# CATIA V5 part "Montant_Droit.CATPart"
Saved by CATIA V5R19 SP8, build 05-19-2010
Part number: Montant_Droit
Nomenclature: 3
Material "Acier": density 7860 kg/m3, Young's modulus 2e+11 Pa, Poisson ratio 0.266, thermal expansion 1.17e-05 1/K
Bounding box of the stored display mesh (mm): x -80.5 to 22.481, y -67.011 to 64.472, z 0 to 1194.396
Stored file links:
  C:\Users\rphgr\Desktop\0_Tapis_TC520B_vitesse\Montant_Droit.CATPart
  D:\Programmes\DassaultSysteme\win_b64\reffiles\standard\MetricThickPitch.txt
  D:\Programmes\DassaultSysteme\win_b64\startup\materials\French\Catalog.CATMaterial
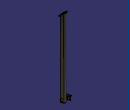
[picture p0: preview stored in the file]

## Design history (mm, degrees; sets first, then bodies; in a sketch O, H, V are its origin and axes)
AxisSystem1: origin (0, 0, 0), X (1, 0, 0), Y (0, 1, 0), Z (0, 0, 1)
Body1 (main body), material "Acier"
  Sketch1 on XY plane of AxisSystem1, origin (0, 0, 0), H (1, 0, 0), V (0, 1, 0)
    construction line L1 (0, 20) -> (0, -20)
    point P1 (0, 20)
    point P2 (0, -20)
    line L2 (20, 20) -> (20, -20)
    line L3 (-20, -20) -> (-20, 20)
    arc A1 centre (0, -20) radius 20 from (20, -20) to (-20, -20) cw
    arc A2 centre (0, 20) radius 20 from (-20, 20) to (20, 20) cw
    distance L1 L2 = 20
    length L1 = 40
    distance P2 O = 20
    coincidence: P1 V
    vertical: L1 V
    tangency: A1 L2, A2 L2, A1 L3, A2 L3
  Pad1: profile Sketch1, direction (0, 0, 1), length 1220, thin wall 1.5
  Sketch2 on YZ plane of AxisSystem1, origin (0, 0, 0), H (0, 1, 0), V (0, 0, 1)
    line L1 (-40, 1110) -> (-40, 0)
    point P2 (-40, 0)
    line L2 (-40, 0) -> (40, 21.4359)
    line L3 (40, 21.4359) -> (40, 1190)
    line L4 (40, 1190) -> (-40, 1110)
    reference intersected line E1 through (0, 0) direction (-1, 0) from XY plane of AxisSystem1
    distance P2 O = 40
    distance L1 L3 = 80
    angle L1 L2 = 75
    length L1 = 1110
    angle L4 L3 = 45
    vertical: L1 V
    coincidence: P2 E1
  Pocket1: profile Sketch2, direction (-1, 0, 0), through (limit type 3), opposite side through (limit type 3), outer side
  Sketch3 on face of Pad1, origin (18.5, 0, 0), H (0, -1, 0), V (0, 0, 1)
    line L1 (-17, 61.6004) -> (17, 61.6004)
    line L2 (20, 58.6004) -> (20, 24.6004)
    line L3 (17, 21.6004) -> (-17, 21.6004)
    line L4 (-20, 24.6004) -> (-20, 58.6004)
    arc A1 centre (-17, 58.6004) radius 3 from (-17, 61.6004) to (-20, 58.6004) ccw
    arc A2 centre (17, 58.6004) radius 3 from (17, 61.6004) to (20, 58.6004) cw
    arc A3 centre (17, 24.6004) radius 3 from (20, 24.6004) to (17, 21.6004) cw
    arc A4 centre (-17, 24.6004) radius 3 from (-17, 21.6004) to (-20, 24.6004) cw
    distance L2 L4 = 40
    distance L3 L1 = 40
    radius A1 = 3
    radius A2 = 3
    radius A3 = 3
    radius A4 = 3
    distance L4 V = 20
    horizontal: L1 H, L3 H
    vertical: L2 V, L4 V
    tangency: A1 L1, A1 L4, A2 L1, A2 L2, A3 L2, A3 L3, A4 L3, A4 L4
  Pad2: profile Sketch3, direction (-1, 0, 0), length 67, thin wall 1.5
  Sketch4 on face of Pad1, origin (-20, 0, 0), H (0, -1, 0), V (0, 0, 1)
  Pocket2: profile Sketch4, direction (1, 0, 0), through (limit type 6)
  Sketch5 on face of Pad2, origin (0, 0, 21.6004), H (1, 0, 0), V (0, -1, 0)
    construction line L1 (-4, 0) -> (4, 0)
    point P2 (4, 0)
    line L2 (-4, 8) -> (4, 8)
    line L3 (4, -8) -> (-4, -8)
    arc A1 centre (4, 0) radius 8 from (4, 8) to (4, -8) cw
    arc A2 centre (-4, 0) radius 8 from (-4, -8) to (-4, 8) cw
    reference intersected line E1 through (0, 0) direction (0, 1) from YZ plane of AxisSystem1
    distance L1 L2 = 8
    length L1 = 8
    distance P2 E1 = 4
    horizontal: L1 H
    tangency: A1 L2, A2 L2, A1 L3, A2 L3
    coincidence: L1 H
  Pocket3: profile Sketch5, direction (0, 0, 1), through (limit type 3)
  Plane1: type Angle, RefPlane face of Pocket1 from Sketch2.L2, Direction edge [XY plane of AxisSystem1 | ZX plane of AxisSystem1], Angle 90
  Sketch6 on Plane1, origin (0, 0, 0), H (1, 0, 0), V (0, -0.2588, 0.9659)
    point P1 (-80.5, 65.3528)
    line L1 (-80.5, 65.3528) -> (-54.5, 65.3528)
    arc A1 centre (-54.5, 59.3528) radius 6 from (-54.5, 65.3528) to (-48.5, 59.3528) cw
    line L2 (-48.5, 59.3528) -> (-48.5, 20.3528)
    point P5 (-48.5, 20.3528)
    reference intersected line E1 through (-48.5, 0) direction (0, -1) from end face of Pad2
    reference intersected line E2 through (0, 10.3528) direction (-1, 0) from face of Pocket1 from Sketch2.L2
    angle L1 L2 = 90
    distance P5 L1 = 45
    distance P1 L2 = 32
    radius A1 = 6
    distance P5 E2 = 10
    tangency: A1 L1, L2 A1
    coincidence: L2 E1
  Pad3: profile Sketch6, direction (0, -0.9659, -0.2588), length 51.864, opposite side length 73.136, thin wall 4
  Fillet1: radius 4, on edge [face of Pad3 | end face of Pad3] (x2); edge [start face of Pad3 | face of Pad3] (x2)
  Sketch7 on face of Pad3, origin (-52.5, 0, 0), H (0, -1, 0), V (0, 0, 1)
    construction line L1 (47.6556, 23.8306) -> (46.8792, 20.9328)
    point P2 (46.8792, 20.9328)
    line L2 (52.0023, 22.6659) -> (51.2258, 19.7681)
    line L3 (42.5325, 22.0975) -> (43.309, 24.9953)
    arc A1 centre (46.8792, 20.9328) radius 4.5 from (51.2258, 19.7681) to (42.5325, 22.0975) cw
    arc A2 centre (47.6556, 23.8306) radius 4.5 from (43.309, 24.9953) to (52.0023, 22.6659) cw
    construction line L4 (-48.9369, 49.7125) -> (-49.7134, 46.8147)
    point P8 (-49.7134, 46.8147)
    line L5 (-44.5903, 48.5478) -> (-45.3667, 45.65)
    line L6 (-54.0601, 47.9794) -> (-53.2836, 50.8772)
    arc A3 centre (-49.7134, 46.8147) radius 4.5 from (-45.3667, 45.65) to (-54.0601, 47.9794) cw
    arc A4 centre (-48.9369, 49.7125) radius 4.5 from (-53.2836, 50.8772) to (-44.5903, 48.5478) cw
    reference intersected line E1 (66.9225, 49.3711) -> (55.3645, 6.2359) from end face of Pad3
    reference intersected line E2 (65.638, 3.4831) -> (-55.1027, 35.8354) from face of Pad3
    reference intersected line E3 (65.638, 3.4831) -> (-55.1027, 35.8354) from face of Pad3
    construction line L7 (-4.6593, 43.0247) -> (5, 40.4365)
    point P14 (5, 40.4365)
    line L8 (-2.0711, 52.684) -> (7.5882, 50.0958)
    line L9 (2.4118, 30.7772) -> (-7.2474, 33.3654)
    arc A5 centre (5, 40.4365) radius 10 from (7.5882, 50.0958) to (2.4118, 30.7772) cw
    arc A6 centre (-4.6593, 43.0247) radius 10 from (-7.2474, 33.3654) to (-2.0711, 52.684) cw
    reference intersected line E4 (65.638, 3.4831) -> (-55.1027, 35.8354) from face of Pad3
    distance L1 L2 = 4.5
    distance L4 L5 = 4.5
    length L1 = 3
    length L4 = 3
    distance L4 L1 = 100
    distance L1 E1 = 12
    distance P2 E2 = 12
    distance P8 E3 = 12
    distance L7 L8 = 10
    distance L7 E4 = 20
    length L7 = 10
    distance P14 V = 5
    tangency: A1 L2, A2 L2, A1 L3, A2 L3, A3 L5, A4 L5, A3 L6, A4 L6, A5 L8, A6 L8, A5 L9, A6 L9
    perpendicularity: L7 L3
  Pocket4: profile Sketch7, direction (1, 0, 0), through (limit type 6)
  Sketch8 on face of Pad3, origin (0, -15.8793, 59.2622), H (-1, 0, 0), V (0, 0.9659, 0.2588)
    construction line L1 (66.8047, 54.136) -> (66.8047, 52.136)
    point P1 (66.8047, 54.136)
    line L2 (71.3047, 54.136) -> (71.3047, 52.136)
    line L3 (62.3047, 52.136) -> (62.3047, 54.136)
    arc A1 centre (66.8047, 52.136) radius 4.5 from (71.3047, 52.136) to (62.3047, 52.136) cw
    arc A2 centre (66.8047, 54.136) radius 4.5 from (62.3047, 54.136) to (71.3047, 54.136) cw
    construction line L4 (66.8047, -30.864) -> (66.8047, -32.864)
    point P7 (66.8047, -30.864)
    point P8 (66.8047, -32.864)
    line L5 (71.3047, -30.864) -> (71.3047, -32.864)
    line L6 (62.3047, -32.864) -> (62.3047, -30.864)
    arc A3 centre (66.8047, -32.864) radius 4.5 from (71.3047, -32.864) to (62.3047, -32.864) cw
    arc A4 centre (66.8047, -30.864) radius 4.5 from (62.3047, -30.864) to (71.3047, -30.864) cw
    reference intersected line E1 (80.5, 73.136) -> (80.5, -51.864) from face of Pad3
    reference intersected line E2 (80.5, -51.864) -> (48.8431, -51.864) from end face of Pad3
    reference projected line E3 (80.5, 73.136) -> (54.5, 73.136) from edge [face of Pad3 | start face of Pad3]
    distance L1 L2 = 4.5
    distance L4 L5 = 4.5
    distance L1 E1 = 13.6953
    length L1 = 2
    length L4 = 2
    distance P8 E2 = 19
    distance P1 E3 = 19
    vertical: L1 V, L4 V
    tangency: A1 L2, A2 L2, A1 L3, A2 L3, A3 L5, A4 L5, A3 L6, A4 L6
    coincidence: P7 L1
  Pocket5: profile Sketch8, direction (0, -0.2588, 0.9659), through (limit type 6)
  Plane2: type Normal, Curve edge [face of Pocket1 from Sketch2.L4 | face of Pad1], RefPoint vertex [face of Pad1 | face of Pocket1 from Sketch2.L4 | face of Pad1]
  Plane3: type Offset, RefPlane face of Pocket1 from Sketch2.L4, Offset 0, reversed
  Sketch9 on Plane2, origin (0, 555, 555), H (-1, 0, 0), V (0, -0.7071, 0.7071)
    arc A1 centre (0, 824.5306) radius 23 from (-22.5834, 820.1728) to (22.5834, 820.1728) ccw
    point P1 (0, 824.5306)
    reference projected point E1 (-20, 813.1728) from edge [face of Pocket1 from Sketch2.L4 | face of Pad1]
    axis line L1 (-28.642, 820.1728) -> (24.6976, 820.1728)
    reference intersected line E2 through (0, 813.1728) direction (1, 0) from face of Pocket1 from Sketch2.L4
    point P4 (22.5834, 820.1728)
    point P5 (-22.5834, 820.1728)
    radius A1 = 23
    distance L1 E2 = 7
    coincidence: P1 V, A1 E1, L1 P4, L1 P5
    horizontal: L1 H
  Pad4: profile Sketch9, direction (0, -0.7071, -0.7071), length 41, opposite side length 95, thin wall 3
  Sketch10 on Plane2, origin (0, 555, 555), H (-1, 0, 0), V (0, -0.7071, 0.7071)
    projected arc E1 centre (0, 824.5306) radius 20 from (-19.6377, 820.7412) to (19.6377, 820.7412) ccw from edge [start face of Pad4 | face of Pad4]
  Pocket6: profile Sketch10, direction (0, 0.7071, 0.7071), length 91, opposite side length 71
  Fillet2: radius 20, on edge [face of Pad4 | start face of Pad4] (x2); edge [end face of Pad4 | face of Pad4] (x2)
  Fillet3: radius 0.5, on face of Pad4
  Sketch11 on Plane3, origin (0, -575, 575), H (-1, 0, 0), V (0, 0.7071, 0.7071)
    construction line L1 (0, 818.1728) -> (0, 808.1728)
    point P1 (0, 818.1728)
    line L2 (10, 818.1728) -> (10, 808.1728)
    line L3 (-10, 808.1728) -> (-10, 818.1728)
    arc A1 centre (0, 808.1728) radius 10 from (10, 808.1728) to (-10, 808.1728) cw
    arc A2 centre (0, 818.1728) radius 10 from (-10, 818.1728) to (10, 818.1728) cw
    reference intersected line E1 through (0, 0) direction (0, -1) from YZ plane of AxisSystem1
    reference intersected line E2 through (0, 813.1728) direction (-1, 0) from ZX plane of AxisSystem1
    distance L1 L2 = 10
    length L1 = 10
    distance P1 E2 = 5
    vertical: L1 V
    tangency: A1 L2, A2 L2, A1 L3, A2 L3
    coincidence: L1 E1
  Pocket7: profile Sketch11, direction (0, -0.7071, 0.7071), length 22, mirrored extent
  Sketch12 on Plane3, origin (5.7218, 33.2205, 1183.2205), H (1, 0, 0), V (0, -0.7071, -0.7071)
    point P1 (-5.7218, 16.9808)
    reference intersected line E1 through (-5.7218, 0) direction (0, 1) from YZ plane of AxisSystem1
    reference projected point E2 (-5.7218, 41.9808) from axis of face of Pocket7 from Sketch11.A2
    distance P1 E2 = 25
    coincidence: P1 E1
  Hole1: placed by Sketch12, at (0, 21.2132, 1171.2132) direction (0, -0.7071, 0.7071), diameter 6.647, through (limit type 6), threaded "M8", thread diameter 8, thread depth -8.3449, pitch 1.25
  Sketch13 on Plane3, origin (1.2244, 36.2824, 1186.2824), H (1, 0, 0), V (0, -0.7071, -0.7071)
    point P1 (-1.2244, 81.311)
    reference intersected line E1 through (-1.2244, 0) direction (0, 1) from YZ plane of AxisSystem1
    reference projected point E2 (-1.2244, 56.311) from axis of face of Pocket7 from Sketch11.A1
    distance E2 P1 = 25
    coincidence: P1 E1
  Hole2: placed by Sketch13, at (0, -21.2132, 1128.7868) direction (0, -0.7071, 0.7071), diameter 6.647, through (limit type 6), threaded "M8", thread diameter 8, thread depth -8.3449, pitch 1.25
